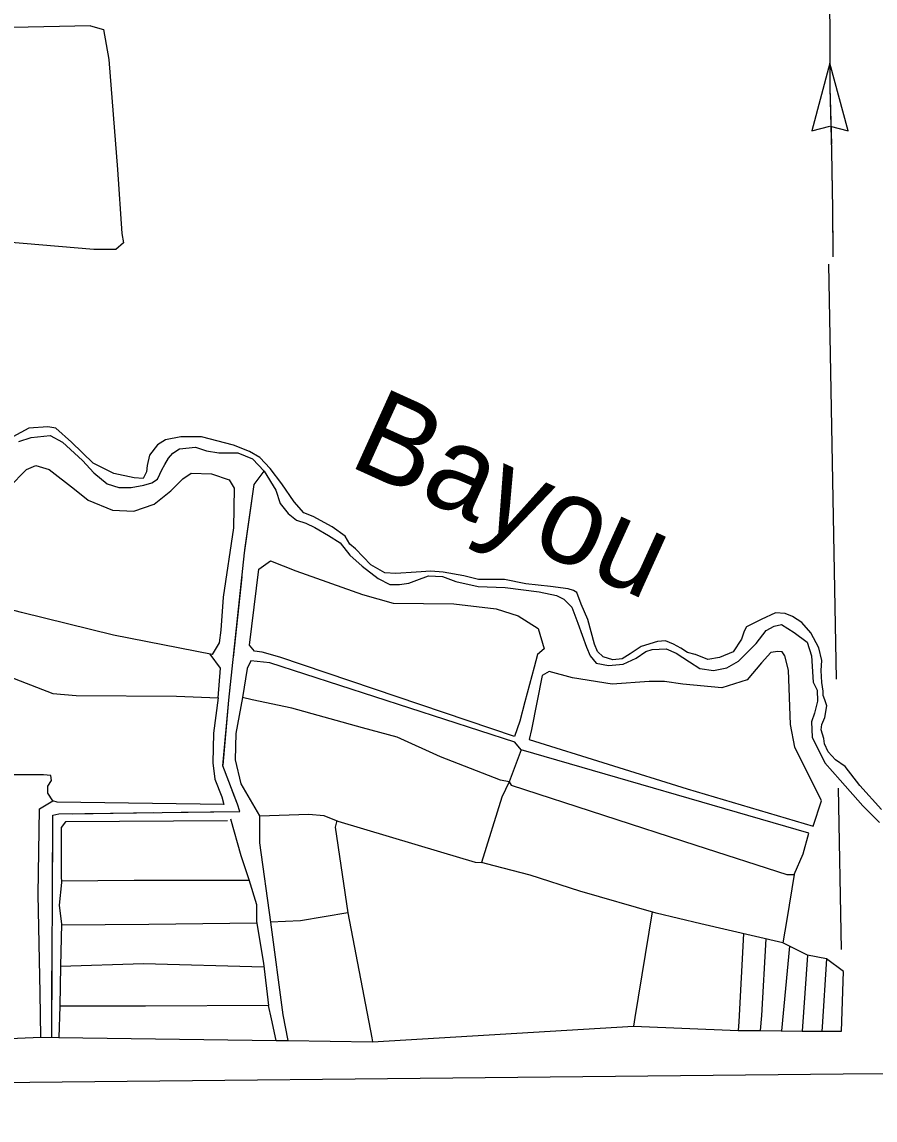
# Model space of a CAD drawing. Extents: x 1127717 to 1741049, y 2026793 to 2244711.
# Drawn here: x 1328788 to 1332953, y 2075463 to 2080824 of the extents above; entities that cross this region are included whole.
import ezdxf

# ---------------------------------------------------------------- set-up
doc = ezdxf.new("R2010")
doc.units = 0
for name, color, linetype in [('15', 7, 'Continuous'), ('35', 7, 'Continuous'), ('43', 7, 'Continuous'), ('5', 7, 'Continuous')]:
    doc.layers.add(name, color=color, linetype=linetype)

msp = doc.modelspace()

# ---------------------------------------------------------------- linework, layer by layer
at = {"layer": '15'}
msp.add_lwpolyline([(1312661.9, 2075431.7), (1316804, 2075463.1), (1322104.8, 2075539.2), (1327394.8, 2075632.9), (1332797, 2075688.9), (1333675.4, 2075694)], dxfattribs=at)
at = {"layer": '35'}
for points in [[(1329123.4, 2080805.2), (1329186.8, 2080786.6), (1329212.9, 2080641.2), (1329253.9, 2080104.5), (1329276.2, 2079791.4), (1329283.7, 2079746.7), (1329246.4, 2079713.1), (1329138.3, 2079713.1), (1328620.4, 2079757.9), (1328098.8, 2079791.4), (1327823.1, 2079858.5), (1327577.2, 2079906.9), (1327469.1, 2079951.7)], [(1329123.4, 2080805.2), (1328285.1, 2080786.6), (1327797, 2080764.2), (1327525, 2080756.7)], [(1329488.4, 2078784.3), (1329449.5, 2078760.3), (1329410.6, 2078709.4), (1329398.6, 2078658.5), (1329395.6, 2078628.6), (1329380.6, 2078595.7), (1329335.8, 2078598.6), (1329237, 2078619.6), (1329135.3, 2078670.5), (1329030.5, 2078772.3), (1328952.7, 2078841.1), (1328913.8, 2078847.1), (1328821, 2078841.1), (1328743.2, 2078799.2)], [(1328773.2, 2078775.3), (1328833, 2078796.2), (1328925.8, 2078805.2), (1328985.6, 2078772.3), (1329084.4, 2078682.5), (1329138.2, 2078622.6), (1329204.1, 2078568.7), (1329260.9, 2078550.7), (1329320.8, 2078550.7), (1329383.6, 2078562.7), (1329422.5, 2078574.7), (1329449.5, 2078592.7), (1329461.4, 2078616.6), (1329470.4, 2078637.6), (1329485.4, 2078664.5), (1329503.3, 2078694.4), (1329524.3, 2078718.4), (1329557.2, 2078739.4), (1329635, 2078748.3), (1329688.9, 2078730.4), (1329748.7, 2078721.4), (1329841.5, 2078721.4), (1329913.3, 2078691.5), (1329970.2, 2078631.6), (1330027, 2078538.8), (1330048, 2078472.9), (1330086.9, 2078425), (1330128.8, 2078392.1), (1330173.7, 2078377.1), (1330218.6, 2078356.2), (1330284.4, 2078317.2), (1330341.3, 2078281.3), (1330389.1, 2078221.4), (1330449, 2078167.5), (1330526.8, 2078107.7), (1330583.7, 2078077.7), (1330631.5, 2078077.7), (1330676.4, 2078083.7), (1330715.3, 2078098.7), (1330772.2, 2078119.6), (1330841, 2078116.6), (1330906.8, 2078092.7), (1331014.6, 2078068.7), (1331146.3, 2078062.8), (1331313.8, 2078041.8), (1331397.6, 2078023.8), (1331433.5, 2078005.9)], [(1332983.7, 2076979), (1332879, 2077095.8), (1332807.1, 2077188.6), (1332759.2, 2077221.5), (1332723.3, 2077260.4), (1332705.4, 2077299.3), (1332702.4, 2077326.3), (1332690.4, 2077368.2), (1332693.4, 2077395.1), (1332708.4, 2077428.1), (1332717.4, 2077485), (1332708.4, 2077514.9), (1332699.4, 2077535.9), (1332699.4, 2077556.8), (1332693.4, 2077598.7), (1332690.4, 2077658.6), (1332693.4, 2077706.5), (1332678.5, 2077769.4), (1332639.5, 2077841.2), (1332594.7, 2077892.1), (1332549.8, 2077922.1), (1332513.9, 2077937), (1332466, 2077940), (1332397.1, 2077907.1), (1332325.3, 2077871.2), (1332313.4, 2077850.2), (1332301.4, 2077811.3), (1332259.5, 2077748.4), (1332193.7, 2077721.5), (1332136.8, 2077712.5), (1332076.9, 2077736.4), (1332074, 2077736.4), (1332038, 2077745.4), (1332005.1, 2077766.4), (1331969.2, 2077787.3), (1331930.3, 2077802.3), (1331891.4, 2077799.3), (1331810.6, 2077775.4), (1331756.7, 2077739.4), (1331717.8, 2077715.5), (1331672.9, 2077709.5), (1331625.1, 2077724.5), (1331598.1, 2077751.4), (1331583.2, 2077787.3), (1331550.3, 2077907.1), (1331517.3, 2077981.9), (1331496.4, 2078038.8), (1331481.4, 2078047.8), (1331454.5, 2078056.8), (1331367.7, 2078068.7), (1331248, 2078080.7), (1331143.3, 2078101.7), (1331083.4, 2078101.7), (1331017.6, 2078101.7), (1330945.8, 2078119.6), (1330844, 2078137.6), (1330784.2, 2078143.6), (1330712.3, 2078137.6), (1330613.6, 2078131.6), (1330559.7, 2078134.6), (1330490.9, 2078173.5), (1330416.1, 2078251.4), (1330389.1, 2078275.3), (1330365.2, 2078314.2), (1330302.4, 2078359.1), (1330209.6, 2078410), (1330164.7, 2078428), (1330116.8, 2078481.9), (1330057, 2078568.7), (1330000.1, 2078643.6), (1329949.2, 2078697.4), (1329898.4, 2078727.4), (1329820.6, 2078757.3), (1329664.9, 2078799.2), (1329563.2, 2078799.2), (1329488.4, 2078784.3)], [(1328723.8, 2078552.1), (1328810.3, 2078638.7), (1328855.7, 2078659.3), (1328921.7, 2078638.7), (1329045.3, 2078543.8), (1329111.3, 2078490.2), (1329230.9, 2078440.7), (1329333.9, 2078436.6), (1329432.9, 2078469.6), (1329515.3, 2078535.6), (1329573, 2078593.3), (1329614.3, 2078622.2), (1329713.2, 2078618.1), (1329799.8, 2078589.2), (1329824.5, 2078548), (1329820.4, 2078354.1), (1329770.9, 2078016), (1329758.6, 2077855.1), (1329750.3, 2077793.3), (1329717.3, 2077735.5)], [(1329923.5, 2077752), (1329898.7, 2077781.1), (1329944.1, 2078152.3), (1330001.8, 2078193.5), (1330125.5, 2078144), (1330451.2, 2078028.5), (1330599.6, 2077987.3), (1330896.4, 2077983.2), (1331102.6, 2077958.4), (1331209.8, 2077925.4), (1331308.7, 2077863.6), (1331337.6, 2077764.6), (1331304.6, 2077735.7), (1331288.1, 2077673.9), (1331242.7, 2077504.8), (1331218, 2077409.9), (1331193.3, 2077335.5)], [(1329717.3, 2077735.5), (1329235, 2077830.4), (1328785.6, 2077941.7), (1328501.1, 2078016), (1328418.7, 2078028.3)], [(1331433.5, 2078005.9), (1331472.4, 2077967), (1331502.4, 2077889.1), (1331544.3, 2077772.4), (1331562.2, 2077730.4), (1331592.1, 2077694.5), (1331652, 2077682.5), (1331723.8, 2077688.5), (1331786.7, 2077718.5), (1331834.5, 2077751.4), (1331864.5, 2077760.4), (1331933.3, 2077763.4), (1331981.2, 2077742.4), (1332047, 2077700.5), (1332097.9, 2077667.6), (1332163.7, 2077658.6), (1332229.6, 2077670.6), (1332286.4, 2077703.5), (1332373.2, 2077790.3), (1332421.1, 2077853.2), (1332460, 2077874.2), (1332495.9, 2077883.1), (1332558.7, 2077844.2), (1332621.6, 2077796.3), (1332642.5, 2077730.4), (1332651.5, 2077601.7), (1332669.5, 2077562.8), (1332672.5, 2077508.9), (1332657.5, 2077449), (1332642.5, 2077407.1), (1332645.5, 2077332.3), (1332708.4, 2077206.5), (1332783.2, 2077122.7), (1332893.9, 2076997), (1332974.7, 2076916.1)], [(1331193.3, 2077335.5), (1330047.2, 2077723.1), (1329960.6, 2077747.9), (1329923.5, 2077752)], [(1331263.7, 2077321.4), (1332035.3, 2077080.2), (1332650.9, 2076898.5), (1332690.9, 2077021.7), (1332561.7, 2077283.4), (1332540.1, 2077394.3), (1332530.9, 2077659.1), (1332512.4, 2077729.9), (1332500.1, 2077748.4), (1332478.6, 2077751.5), (1332444.7, 2077745.3), (1332398.5, 2077696), (1332327.7, 2077612.9), (1332204.6, 2077572.9), (1332013.8, 2077591.3), (1331924.5, 2077603.7), (1331850.6, 2077603.7), (1331669, 2077591.3), (1331475.1, 2077622.1), (1331361.2, 2077652.9), (1331327.4, 2077634.4), (1331275.1, 2077369.6), (1331263.7, 2077321.4)], [(1329773, 2077003.7), (1328960.4, 2077016), (1328938.8, 2077022.1), (1328914.2, 2077059.1), (1328914.2, 2077093), (1328932.7, 2077120.7), (1328929.6, 2077145.3), (1328892.7, 2077148.4), (1328443.3, 2077148.4), (1328415.6, 2077169.9), (1328412.5, 2077210), (1328415.6, 2077668.8), (1328427.9, 2077699.6), (1328455.6, 2077711.9), (1328538.7, 2077699.6), (1328938.8, 2077545.6), (1329052.7, 2077536.4), (1329542.1, 2077533.3), (1329745.3, 2077524.1)], [(1329745.3, 2077524.1), (1329757.6, 2077668.8), (1329707.7, 2077737.4)], [(1331225.8, 2077271.1), (1331195, 2077308), (1329997.7, 2077696), (1329905.3, 2077705.3), (1329886.9, 2077668.3), (1329865.3, 2077526.7), (1329831.5, 2077351.2), (1329828.4, 2077221.8), (1329856.1, 2077104.8), (1329948.4, 2076947.8), (1330188.5, 2076957), (1330262.4, 2076950.8), (1330330.1, 2076923.1), (1330831.8, 2076772.3), (1331001.1, 2076723), (1331031.9, 2076719.9)], [(1329745.3, 2077524.1), (1329723.7, 2077351.6), (1329720.7, 2077206.9), (1329729.9, 2077126.8), (1329763.8, 2077040.6), (1329773, 2077003.7)], [(1331167.3, 2077114), (1331124.2, 2077123.3), (1330831.8, 2077237.2), (1330619.4, 2077332.7), (1330450.1, 2077378.9), (1330105.4, 2077474.3), (1329911.5, 2077514.4), (1329865.3, 2077526.7)], [(1332629.4, 2076864.6), (1331225.8, 2077271.1), (1331167.3, 2077114), (1331176.6, 2077098.7), (1332078.4, 2076806.1), (1332521.7, 2076661.4), (1332558.6, 2076661.4), (1332601.7, 2076763)], [(1331167.3, 2077114), (1331130.4, 2077040.1), (1331031.9, 2076719.9)], [(1328880.2, 2075868.1), (1328877.3, 2076084), (1328868, 2076564.4), (1328873.2, 2076982.6), (1328938.8, 2077022.1)], [(1329948.4, 2076947.8), (1329948.4, 2076816.9), (1330001, 2076428.9)], [(1329791.5, 2076924.7), (1329000.4, 2076918.5), (1328978.9, 2076890.8), (1328978.9, 2076653.7), (1328981.9, 2076622.9), (1328969.6, 2076512.1), (1328981.9, 2076419.7), (1328975.8, 2076216.4), (1328972.7, 2076019.4)], [(1329806.8, 2076933.9), (1329856.1, 2076755.3), (1329896.1, 2076638.3), (1329933, 2076515.1), (1329933, 2076432), (1329966.9, 2076228.8), (1329991.5, 2076022.4)], [(1330324.9, 2076925.3), (1330317.8, 2076893.9), (1330379.4, 2076475.1), (1330496.3, 2075865.4), (1330499.2, 2075845.9)], [(1327565.7, 2076837.9), (1327555, 2075848.3), (1327590.3, 2075813), (1328880.2, 2075868.1), (1328968, 2075866.9), (1330029.5, 2075852.3), (1330086.1, 2075851.6), (1330499.2, 2075845.9), (1331772.8, 2075920.9), (1332284.2, 2075900.6), (1332392.2, 2075899.7), (1332596.8, 2075898), (1332692.6, 2075897.3), (1332789.3, 2075896.5)], [(1332601.7, 2076763), (1332629.4, 2076864.6)], [(1332558.6, 2076661.4), (1332521.7, 2076442.8), (1332503.2, 2076328.8), (1332103, 2076421.2), (1331884.5, 2076473.6), (1331512.1, 2076581.3), (1331268.9, 2076658.3), (1331093.5, 2076704.5), (1331031.9, 2076719.9)], [(1329897.8, 2076632.7), (1329335.9, 2076632.1), (1328981.3, 2076629)], [(1330379.4, 2076475.1), (1330148.5, 2076435.1), (1330000.8, 2076428.9)], [(1331865, 2076479.2), (1331779.9, 2075963.9), (1331772.8, 2075920.9)], [(1328981.8, 2076416.5), (1329406.7, 2076419.7), (1329934.1, 2076425.5)], [(1330000.8, 2076428.9), (1330062.3, 2075976.3), (1330086.1, 2075851.6)], [(1332310, 2076373.4), (1332287.7, 2075942.4), (1332284.2, 2075900.6)], [(1332419.9, 2076348.1), (1332398.5, 2075973.2), (1332392.2, 2075899.7)], [(1332535.8, 2076312.5), (1332495.9, 2075898.9)], [(1332789.3, 2075896.5), (1332798.7, 2076188.7), (1332715.6, 2076250.3), (1332623.2, 2076268.8), (1332503.2, 2076328.8)], [(1332623.2, 2076268.8), (1332596.8, 2075898)], [(1332715.6, 2076250.3), (1332694, 2075917.8), (1332692.6, 2075897.3)], [(1329969.1, 2076210.5), (1329382.1, 2076225.7), (1328975.7, 2076213.5)], [(1328972.7, 2076019.4), (1328968, 2075866.9)], [(1329991.5, 2076022.4), (1329391.3, 2076019.4), (1328972.7, 2076019.4)], [(1330029.5, 2075852.3), (1330006.9, 2075957.8), (1329991.5, 2076022.4)]]:
    msp.add_lwpolyline(points, dxfattribs=at)
at = {"layer": '43'}
for p, q in [((1332732.3, 2080623.5), (1332643.5, 2080292)), ((1332821.2, 2080292), (1332732.3, 2080623.5)), ((1332643.5, 2080292), (1332731.7, 2080315.7)), ((1332732.9, 2080315.7), (1332821.2, 2080292))]:
    msp.add_line(p, q, dxfattribs=at)
for points in [[(1332717.6, 2081150.8), (1332721.9, 2081133.6), (1332726.1, 2080987.5), (1332732.3, 2080818.5), (1332732.3, 2080755.5)], [(1332726.1, 2080987.5), (1332732.3, 2080818.5), (1332732.3, 2080503.3), (1332740.7, 2080192.3), (1332744.9, 2079912.6), (1332747, 2079676.8)], [(1332732.3, 2080623.5), (1332732.3, 2080503.3), (1332739.7, 2080227.6)], [(1332742.1, 2080095.7), (1332744.9, 2079912.6), (1332746.7, 2079699.7)], [(1328933.8, 2075867.3), (1328938.8, 2076952.1), (1328968, 2076958), (1329851.3, 2076969.7), (1329839.6, 2077004.8), (1329769.4, 2077192.1), (1329798.6, 2077513.9), (1329874.7, 2078232.2), (1329921.5, 2078565.8), (1329970.2, 2078631.6)], [(1329876.8, 2078247), (1329921.5, 2078565.8), (1329965.5, 2078625.3)], [(1329841.5, 2077918.9), (1329862.4, 2078115.8)], [(1329820.7, 2077722), (1329841.5, 2077918.9)], [(1329769.8, 2077196.5), (1329798.6, 2077513.9), (1329806.8, 2077590.7)], [(1329564.7, 2076965.9), (1329851.3, 2076969.7), (1329839.6, 2077004.8), (1329814.2, 2077072.6)], [(1329036.8, 2076958.9), (1329432.7, 2076964.1)], [(1328936.8, 2076522.7), (1328938.6, 2076918.7)], [(1328934.4, 2075994.7), (1328936.2, 2076390.7)]]:
    msp.add_lwpolyline(points, dxfattribs=at)
at = {"layer": '5'}
for points in [[(1332725.8, 2079642.2), (1332762.9, 2077615.4)], [(1332772.6, 2077083.1), (1332787, 2076296.4)]]:
    msp.add_lwpolyline(points, dxfattribs=at)

# ---------------------------------------------------------------- texts
at = {"layer": '35'}
msp.add_text('Bayou', height=422.4, rotation=335.6122, dxfattribs=at).set_placement((1330374.5, 2078660.8))

doc.saveas('drawing.dxf')
